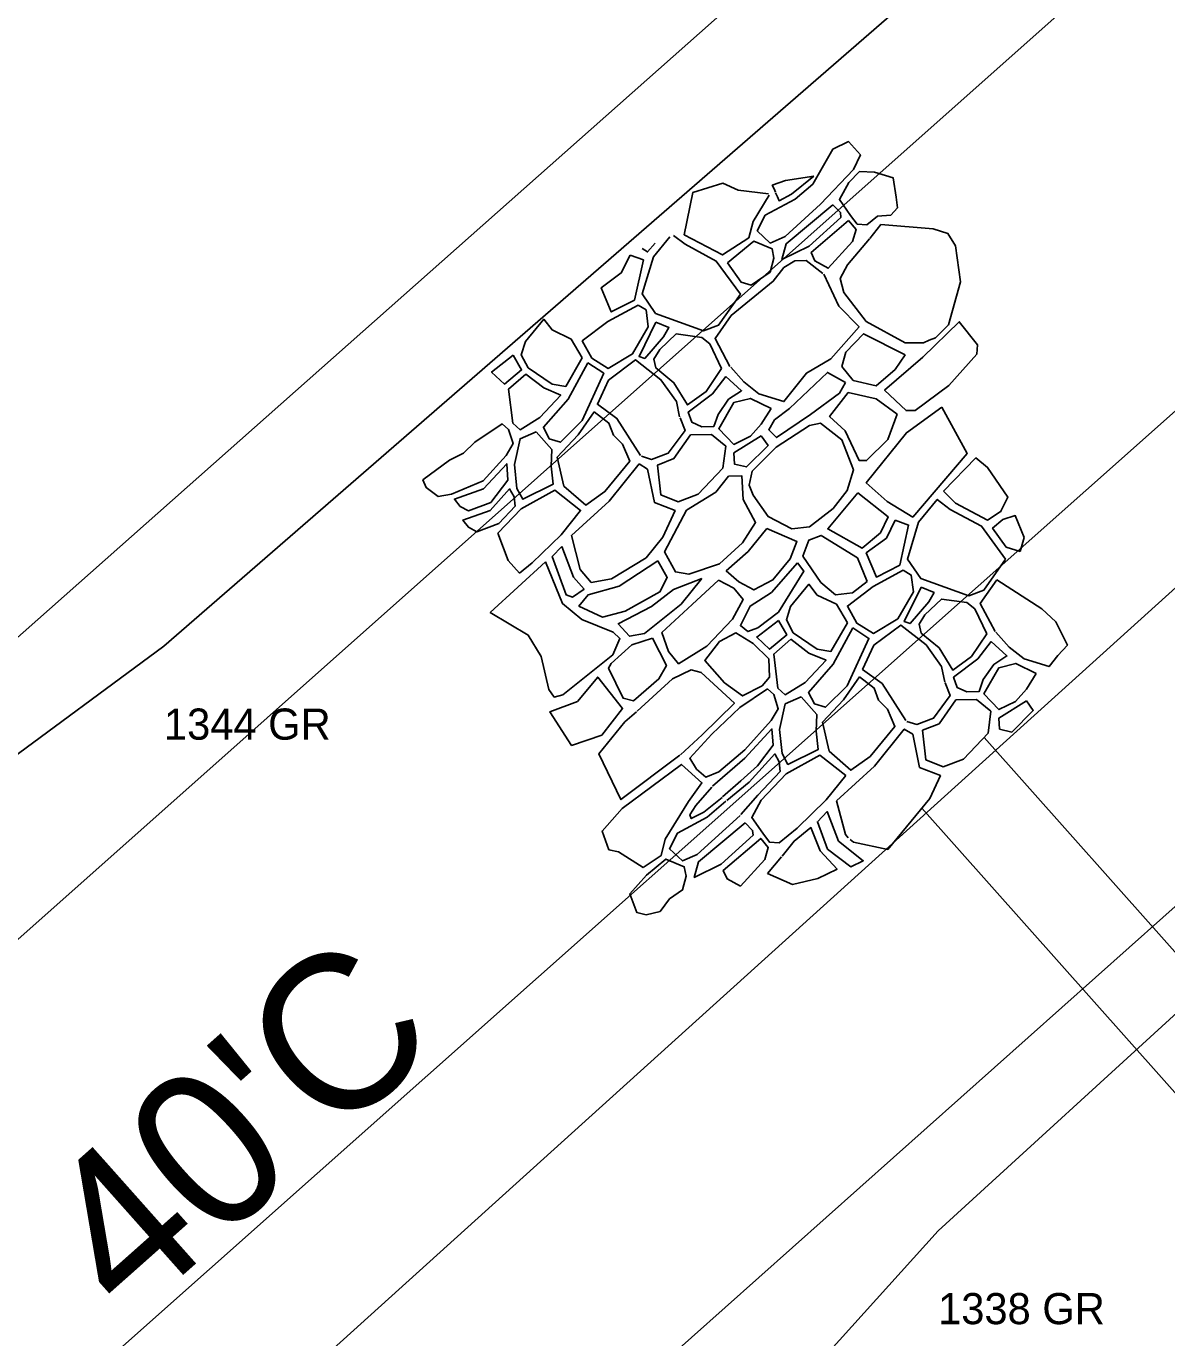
# Model space of a CAD drawing. Extents: x 50001 to 56005, y 49075 to 53926.
# Drawn here: x 53395.53 to 53432.14, y 51442.52 to 51484.63 of the extents above; entities that cross this region are included whole.
import ezdxf

# ---------------------------------------------------------------- set-up
doc = ezdxf.new("R2010")
doc.units = 0
for name, color, linetype in [('Level 1', 7, 'Continuous'), ('Level 11', 7, 'Continuous'), ('Level 16', 7, 'Continuous'), ('Level 18', 7, 'Continuous'), ('Level 3', 7, 'Continuous'), ('Level 57', 7, 'Continuous'), ('Level 7', 7, 'Continuous'), ('Level 8', 7, 'Continuous')]:
    doc.layers.add(name, color=color, linetype=linetype)

msp = doc.modelspace()

# ---------------------------------------------------------------- linework, layer by layer
at = {"layer": 'Level 1'}
msp.add_line((52544.807, 50683.302), (55534.583, 53340.862), dxfattribs=at)
at = {"layer": 'Level 11'}
msp.add_line((53157.705, 51254.454), (53424.495, 51490.929), dxfattribs=at)
at = {"layer": 'Level 16'}
for points in [[(53420.783, 51479.562), (53421.418, 51480.678), (53421.926, 51480.925), (53422.308, 51480.501), (53422.089, 51480.027), (53421.028, 51478.913)], [(53422.273, 51479.969), (53421.938, 51479.616), (53421.636, 51479.068), (53421.993, 51478.555), (53422.205, 51478.275), (53422.518, 51478.253), (53422.854, 51478.526)], [(53422.273, 51479.969), (53422.759, 51479.947), (53423.357, 51479.761), (53423.455, 51479.144), (53423.496, 51478.796), (53423.286, 51478.563), (53422.854, 51478.526)], [(53416.651, 51477.927), (53416.926, 51479.286), (53417.888, 51479.595), (53418.382, 51479.368), (53419.357, 51479.242)], [(53420.783, 51479.562), (53420.209, 51479.076), (53419.253, 51478.561), (53418.995, 51478.058), (53419.411, 51477.667), (53419.889, 51477.875), (53421.028, 51478.913)], [(53419.583, 51479.306), (53419.535, 51479.403), (53419.477, 51479.521), (53419.905, 51479.678), (53420.809, 51479.811)], [(53419.583, 51479.277), (53419.646, 51479.149), (53419.695, 51479.027), (53420.099, 51479.236), (53420.809, 51479.811)], [(53420.769, 51479.786), (53420.7, 51479.726)], [(53416.651, 51477.927), (53417.879, 51477.285), (53418.725, 51477.837), (53418.861, 51478.364), (53419.377, 51479.201)], [(53416.195, 51477.863), (53415.662, 51477.221), (53415.305, 51476.032), (53415.733, 51475.408), (53417.276, 51474.846), (53417.754, 51475.031), (53418.454, 51476.024), (53417.683, 51477.089), (53416.679, 51477.627), (53416.308, 51477.91)], [(53422.609, 51477.818), (53422.965, 51478.264)], [(53424.513, 51474.547), (53424.717, 51474.622), (53425.13, 51475.041), (53425.518, 51476.424), (53425.359, 51477.579), (53425.117, 51477.977), (53424.64, 51478.121), (53422.965, 51478.264)], [(53415.302, 51477.488), (53415.478, 51477.38), (53415.72, 51477.663)], [(53424.513, 51474.547), (53424.334, 51474.461), (53423.746, 51474.461), (53422.487, 51475.152), (53421.775, 51476.075), (53421.66, 51476.526), (53421.891, 51476.967), (53422.594, 51477.802)], [(53421.102, 51476.692), (53420.562, 51477.104), (53420.207, 51477.092), (53419.851, 51476.883), (53419.508, 51476.442), (53418.159, 51475.337), (53417.643, 51474.602), (53418.12, 51473.706)], [(53421.128, 51476.666), (53421.617, 51475.645), (53422.267, 51474.973), (53421.363, 51473.944), (53420.575, 51473.491), (53419.85, 51472.577), (53419.052, 51472.828), (53418.57, 51473.206), (53418.146, 51473.68)], [(53424.311, 51474.007), (53425.478, 51475.141), (53426.068, 51474.396), (53426.043, 51474.104), (53425.149, 51473.095)], [(53416.503, 51472.083), (53416.404, 51472.579), (53415.902, 51473.276), (53415.094, 51473.913), (53414.224, 51473.262), (53413.867, 51472.49), (53414.492, 51472.037), (53415.254, 51470.847)], [(53424.311, 51474.007), (53423.083, 51472.938), (53423.775, 51472.288), (53424.069, 51472.288), (53425.149, 51473.095)], [(53416.518, 51472.057), (53416.68, 51471.651), (53416.142, 51470.923), (53415.605, 51470.722), (53415.281, 51470.819)], [(53410.199, 51470.031), (53410.936, 51470.846), (53411.16, 51471.226), (53411.015, 51471.684), (53410.814, 51471.862), (53409.931, 51471.269), (53409.568, 51470.924)], [(53410.199, 51470.031), (53409.185, 51469.609), (53408.752, 51469.525), (53408.368, 51469.815), (53408.267, 51470.064), (53409.122, 51470.698), (53409.568, 51470.924)], [(53424.97, 51469.704), (53426.012, 51470.766), (53426.391, 51470.465), (53427.042, 51469.504), (53426.808, 51469.037)], [(53410.212, 51469.774), (53410.958, 51470.578), (53410.991, 51470.052), (53410.445, 51469.337)], [(53410.445, 51469.337), (53409.725, 51469.065), (53409.459, 51469.212), (53409.278, 51469.444), (53410.212, 51469.774)], [(53410.704, 51468.662), (53411.225, 51469.215), (53411.191, 51469.516), (53411.046, 51469.773), (53410.424, 51469.082)], [(53411.362, 51467.065), (53411.77, 51467.394), (53412.698, 51468.3), (53413.325, 51469.083), (53412.499, 51469.73), (53411.414, 51469.137), (53410.667, 51468.348)], [(53424.97, 51469.704), (53425.362, 51469.311), (53426.391, 51468.774), (53426.828, 51469.059)], [(53410.704, 51468.662), (53409.994, 51468.394), (53409.728, 51468.54), (53409.547, 51468.773), (53410.424, 51469.082)], [(53426.875, 51468.786), (53426.55, 51468.516), (53426.99, 51467.904), (53427.436, 51467.768)], [(53426.875, 51468.786), (53427.277, 51468.917), (53427.558, 51468.217), (53427.436, 51467.768)], [(53410.667, 51468.348), (53411.002, 51467.47), (53411.362, 51467.065)], [(53412.199, 51467.429), (53410.428, 51465.809), (53411.648, 51465.079), (53412.064, 51464.387), (53412.305, 51463.327), (53412.481, 51463.087), (53412.756, 51463.158)], [(53412.199, 51467.429), (53412.743, 51466.092), (53413.364, 51465.576), (53414.376, 51465.177), (53414.586, 51464.967), (53414.364, 51464.45), (53412.756, 51463.158)], [(53426.689, 51466.852), (53426.155, 51466.09), (53426.632, 51465.195)], [(53428.644, 51464.423), (53428.953, 51464.758), (53428.58, 51465.507), (53428.132, 51465.924), (53426.689, 51466.852)], [(53425.015, 51463.572), (53424.915, 51464.067), (53424.414, 51464.765), (53423.606, 51465.401), (53422.735, 51464.751), (53422.379, 51463.978), (53423.003, 51463.526), (53423.766, 51462.336)], [(53428.644, 51464.423), (53428.361, 51464.066), (53427.564, 51464.317), (53427.081, 51464.694), (53426.658, 51465.169)], [(53414.003, 51461.87), (53414.674, 51462.725), (53413.877, 51463.732), (53413.228, 51462.95)], [(53416.532, 51461.238), (53417.224, 51461.874), (53418.264, 51462.891), (53417.192, 51463.873), (53416.88, 51463.962), (53416.276, 51463.671), (53415.137, 51462.632)], [(53425.03, 51463.545), (53425.192, 51463.139), (53424.654, 51462.411), (53424.116, 51462.21), (53423.793, 51462.307)], [(53414.003, 51461.87), (53413.035, 51461.534), (53412.342, 51462.615), (53413.228, 51462.95)], [(53415.12, 51462.615), (53414.749, 51462.296), (53413.914, 51461.266), (53414.623, 51459.796), (53416.514, 51461.22)], [(53417.563, 51460.225), (53418.597, 51461.127), (53419.469, 51462.066), (53419.502, 51461.541), (53418.999, 51460.881), (53418.473, 51460.4), (53417.883, 51459.886)], [(53421.914, 51458.572), (53421.825, 51458.677), (53421.542, 51459.762), (53422.755, 51460.87), (53423.715, 51462.062), (53423.989, 51461.894), (53424.209, 51460.83), (53424.873, 51460.567), (53424.538, 51459.835)], [(53418.474, 51459.314), (53419.02, 51459.943), (53419.736, 51460.703), (53419.703, 51461.005), (53419.558, 51461.262), (53418.741, 51460.356), (53418.018, 51459.769)], [(53415.333, 51457.622), (53415.908, 51457.997), (53416.043, 51458.524), (53416.792, 51459.738), (53417.221, 51460.338), (53416.561, 51460.926), (53414.665, 51459.512)], [(53417.538, 51460.2), (53417.025, 51459.603), (53416.828, 51459.309), (53416.877, 51459.186), (53417.282, 51459.395), (53417.865, 51459.868)], [(53421.977, 51458.513), (53422.086, 51458.428), (53423.184, 51458.199), (53424.538, 51459.835)], [(53415.333, 51457.622), (53414.542, 51458.115), (53414.238, 51458.188), (53414.016, 51458.784), (53414.665, 51459.512)], [(53417.993, 51459.744), (53417.392, 51459.236), (53416.435, 51458.72), (53416.178, 51458.218), (53416.594, 51457.826), (53417.072, 51458.035), (53418.449, 51459.289)], [(53421.248, 51458.205), (53420.93, 51459.087), (53421.236, 51459.414), (53421.599, 51458.463)], [(53418.455, 51457.02), (53419.24, 51457.878), (53419.351, 51458.258), (53419.106, 51458.552), (53417.904, 51457.521), (53418.027, 51457.252), (53418.455, 51457.02)], [(53419.791, 51457.977), (53420.181, 51458.465), (53420.719, 51458.897), (53421.02, 51458.156)], [(53420.133, 51457.076), (53420.939, 51457.265), (53421.561, 51457.566), (53421.02, 51458.156)], [(53421.248, 51458.205), (53421.996, 51457.637), (53422.4, 51457.832), (53421.599, 51458.463)], [(53416.176, 51456.612), (53416.593, 51456.895), (53416.716, 51457.336), (53416.655, 51457.642), (53416.067, 51457.887), (53415.444, 51457.372)], [(53419.325, 51457.426), (53419.776, 51457.962)], [(53416.176, 51456.612), (53415.878, 51456.206), (53415.432, 51456.1), (53415.128, 51456.172), (53414.906, 51456.769), (53415.444, 51457.372)], [(53419.325, 51457.426), (53420.133, 51457.076)]]:
    msp.add_lwpolyline(points, dxfattribs=at)
for points in [[(53421.422, 51478.894), (53419.926, 51477.643), (53419.79, 51477.14), (53420.661, 51477.57), (53421.679, 51478.49), (53421.667, 51478.649)], [(53421.924, 51478.392), (53420.722, 51477.362), (53420.844, 51477.092), (53421.273, 51476.86), (53422.058, 51477.719), (53422.168, 51478.099)], [(53418.038, 51477.028), (53418.479, 51476.416), (53418.797, 51476.318), (53419.41, 51476.735), (53419.533, 51477.177), (53419.472, 51477.483), (53418.884, 51477.727)], [(53414.914, 51477.282), (53415.343, 51477.123), (53415.06, 51475.836), (53414.312, 51475.455), (53413.982, 51476.227), (53414.632, 51476.706)], [(53415.17, 51475.677), (53414.201, 51475.149), (53413.38, 51474.523), (53413.685, 51473.972), (53414.212, 51473.642), (53414.997, 51474.108), (53415.5, 51474.979), (53415.427, 51475.518)], [(53413.379, 51473.984), (53413.024, 51474.584), (53412.412, 51474.877), (53412.143, 51475.22), (53411.554, 51474.509), (53411.419, 51474.08), (53411.639, 51473.664), (53412.41, 51473.138), (53412.851, 51473.065)], [(53415.745, 51475.126), (53415.205, 51474.023), (53415.388, 51473.962), (53415.99, 51474.661), (53416.161, 51474.955)], [(53417.851, 51473.634), (53417.36, 51472.898), (53416.759, 51472.469), (53416.319, 51473.179), (53415.743, 51473.656), (53415.682, 51473.938), (53415.867, 51474.244), (53416.394, 51474.747), (53417.215, 51474.638), (53417.472, 51474.43)], [(53423.746, 51474.083), (53422.403, 51474.753), (53421.835, 51474.165), (53421.709, 51473.703), (53422.076, 51473.252), (53422.81, 51473.085), (53423.42, 51473.61)], [(53411.163, 51474.064), (53410.47, 51473.526), (53410.883, 51473.136), (53411.431, 51473.595)], [(53413.554, 51473.821), (53412.927, 51472.658), (53412.132, 51471.752), (53412.322, 51471.383), (53412.679, 51471.272), (53413.373, 51471.966), (53414.067, 51473.486)], [(53411.565, 51473.461), (53411.017, 51472.98), (53411.149, 51471.885), (53411.384, 51471.673), (53412.021, 51472.065), (53412.692, 51472.78), (53412.145, 51473.014)], [(53417.993, 51473.383), (53417.562, 51472.827), (53416.784, 51472.238), (53416.899, 51471.913), (53417.214, 51471.766), (53417.602, 51471.777), (53417.739, 51472.166), (53418.076, 51472.649), (53418.496, 51472.922)], [(53421.824, 51473.188), (53421.247, 51473.513), (53420.028, 51472.357), (53419.555, 51471.989), (53419.366, 51471.674), (53419.618, 51471.422), (53420.71, 51472.158), (53421.635, 51472.852)], [(53423.492, 51472.172), (53422.81, 51472.665), (53421.918, 51472.863), (53421.319, 51472.096), (53421.822, 51471.635), (53422.272, 51470.68), (53422.503, 51470.68), (53423.186, 51471.363)], [(53419.44, 51472.356), (53418.779, 51472.681), (53418.244, 51472.544), (53417.76, 51471.704), (53418.242, 51471.2), (53418.778, 51471.463), (53419.125, 51471.852)], [(53424.925, 51472.398), (53423.784, 51471.576), (53422.496, 51469.97), (53423.169, 51469.37), (53423.989, 51468.869), (53425.732, 51470.905)], [(53413.764, 51472.245), (53413.249, 51471.507), (53412.578, 51470.792), (53412.789, 51469.865), (53413.493, 51469.251), (53414.108, 51469.687), (53414.902, 51470.66), (53414.668, 51471.207), (53414.378, 51471.498), (53414.233, 51471.888)], [(53411.898, 51471.606), (53411.383, 51471.382), (53411.204, 51470.555), (53411.281, 51469.785), (53411.471, 51469.439), (53412.443, 51469.92), (53412.377, 51470.501), (53412.4, 51471.037)], [(53421.025, 51471.886), (53420.678, 51471.812), (53419.607, 51471.118), (53418.829, 51470.34), (53418.734, 51469.889), (53418.86, 51469.574), (53419.342, 51468.882), (53420.107, 51468.494), (53420.674, 51468.558), (53421.431, 51469.147), (53421.883, 51469.724), (53422.083, 51470.386), (53421.706, 51471.351)], [(53416.859, 51471.514), (53416.321, 51470.744), (53415.794, 51470.532), (53415.898, 51469.584), (53416.457, 51469.363), (53417.1, 51469.607), (53417.891, 51470.44), (53417.987, 51471.146), (53417.523, 51471.525)], [(53419.124, 51471.474), (53418.242, 51470.927), (53418.262, 51470.571), (53418.651, 51470.477), (53419.344, 51471.17)], [(53415.204, 51470.574), (53415.478, 51470.406), (53415.698, 51469.341), (53416.361, 51469.079), (53415.97, 51468.225), (53415.432, 51467.56), (53414.314, 51466.884), (53413.671, 51466.768), (53413.314, 51467.189), (53413.03, 51468.274), (53414.243, 51469.382)], [(53418.07, 51470.177), (53417.669, 51469.67), (53416.73, 51469.09), (53416.023, 51467.751), (53416.37, 51467.108), (53416.802, 51467.035), (53417.782, 51467.363), (53418.521, 51468.038), (53418.943, 51468.692), (53418.543, 51469.429), (53418.502, 51470.188)], [(53422.226, 51469.651), (53421.257, 51468.486), (53422.359, 51467.875), (53422.948, 51468.365), (53423.193, 51468.88)], [(53426.965, 51467.512), (53426.195, 51468.577), (53425.191, 51469.115), (53424.774, 51469.433), (53424.173, 51468.71), (53423.816, 51467.521), (53424.245, 51466.897), (53425.788, 51466.335), (53426.266, 51466.519)], [(53423.426, 51468.77), (53423.854, 51468.611), (53423.571, 51467.325), (53422.823, 51466.944), (53422.493, 51467.715), (53423.143, 51468.194)], [(53419.301, 51468.502), (53418.71, 51467.764), (53418.003, 51467.141), (53418.403, 51466.784), (53418.888, 51466.531), (53419.499, 51466.848), (53420.048, 51467.523), (53420.27, 51468.082)], [(53422.529, 51466.797), (53422.211, 51467.556), (53421.048, 51468.277), (53420.656, 51468.13), (53420.46, 51467.615), (53421.034, 51466.77), (53421.512, 51466.367), (53422.051, 51466.441)], [(53412.724, 51467.926), (53413.102, 51466.936), (53413.439, 51466.557), (53413.07, 51466.293), (53412.859, 51466.377), (53412.418, 51467.599)], [(53415.801, 51467.466), (53416.106, 51466.929), (53415.874, 51466.465), (53414.756, 51465.852), (53414.028, 51465.651), (53413.27, 51466.008), (53413.566, 51466.367), (53414.567, 51466.653)], [(53420.291, 51467.396), (53419.452, 51466.446), (53418.77, 51466.009), (53418.457, 51465.383), (53418.691, 51465.193), (53419.015, 51465.317), (53419.675, 51465.82), (53420.492, 51467.128)], [(53423.681, 51467.165), (53422.713, 51466.638), (53421.891, 51466.012), (53422.197, 51465.461), (53422.723, 51465.131), (53423.508, 51465.597), (53424.011, 51466.467), (53423.938, 51467.006)], [(53417.213, 51466.898), (53416.306, 51466.539), (53415.599, 51466.001), (53414.534, 51465.441), (53414.892, 51465.041), (53415.377, 51465.126), (53416.558, 51466.075)], [(53417.75, 51466.846), (53418.245, 51466.583), (53418.54, 51466.225), (53418.202, 51465.593), (53417.379, 51464.727), (53416.472, 51464.157), (53416.145, 51464.547), (53415.935, 51465.158), (53416.906, 51466.065)], [(53421.891, 51465.473), (53421.536, 51466.073), (53420.924, 51466.366), (53420.655, 51466.709), (53420.066, 51465.997), (53419.93, 51465.568), (53420.15, 51465.152), (53420.922, 51464.626), (53421.363, 51464.553)], [(53424.257, 51466.615), (53423.716, 51465.511), (53423.9, 51465.45), (53424.501, 51466.149), (53424.673, 51466.444)], [(53426.362, 51465.122), (53425.871, 51464.387), (53425.27, 51463.957), (53424.83, 51464.667), (53424.255, 51465.145), (53424.194, 51465.426), (53424.378, 51465.733), (53424.905, 51466.236), (53425.726, 51466.126), (53425.983, 51465.918)], [(53419.675, 51465.552), (53418.981, 51465.015), (53419.394, 51464.624), (53419.942, 51465.083)], [(53422.065, 51465.309), (53421.438, 51464.146), (53420.644, 51463.24), (53420.833, 51462.872), (53421.191, 51462.761), (53421.884, 51463.454), (53422.579, 51464.974)], [(53415.63, 51464.978), (53414.976, 51464.767), (53414.311, 51464.165), (53414.227, 51464.018), (53414.689, 51463.049), (53415.027, 51462.965), (53415.839, 51463.672), (53416.082, 51464.104)], [(53419.393, 51463.731), (53419.372, 51464.312), (53418.869, 51464.814), (53418.311, 51465.148), (53417.786, 51464.868), (53417.316, 51464.265), (53417.941, 51463.55), (53418.521, 51463.126), (53419.158, 51463.451)], [(53420.076, 51464.949), (53419.528, 51464.468), (53419.661, 51463.373), (53419.895, 51463.161), (53420.533, 51463.553), (53421.204, 51464.269), (53420.657, 51464.503)], [(53426.504, 51464.872), (53426.073, 51464.315), (53425.296, 51463.726), (53425.411, 51463.401), (53425.725, 51463.255), (53426.114, 51463.265), (53426.251, 51463.654), (53426.587, 51464.137), (53427.007, 51464.411)], [(53427.952, 51463.845), (53427.291, 51464.17), (53426.755, 51464.032), (53426.271, 51463.192), (53426.754, 51462.689), (53427.289, 51462.952), (53427.636, 51463.341)], [(53422.276, 51463.734), (53421.761, 51462.996), (53421.09, 51462.28), (53421.301, 51461.353), (53422.004, 51460.739), (53422.619, 51461.176), (53423.413, 51462.149), (53423.18, 51462.696), (53422.889, 51462.986), (53422.745, 51463.377)], [(53419.326, 51463.351), (53418.442, 51462.758), (53417.536, 51461.896), (53416.832, 51461.125), (53417.044, 51460.778), (53417.345, 51460.522), (53417.759, 51460.69), (53418.597, 51461.395), (53419.447, 51462.334), (53419.671, 51462.714), (53419.527, 51463.172)], [(53420.409, 51463.095), (53419.895, 51462.871), (53419.715, 51462.044), (53419.793, 51461.273), (53419.982, 51460.927), (53420.955, 51461.409), (53420.888, 51461.989), (53420.911, 51462.526)], [(53425.371, 51463.002), (53424.833, 51462.232), (53424.305, 51462.021), (53424.41, 51461.073), (53424.968, 51460.852), (53425.611, 51461.095), (53426.403, 51461.929), (53426.498, 51462.635), (53426.035, 51463.014)], [(53427.636, 51462.963), (53426.753, 51462.416), (53426.774, 51462.059), (53427.162, 51461.965), (53427.856, 51462.659)], [(53421.836, 51460.572), (53421.01, 51461.219), (53419.926, 51460.625), (53419.121, 51459.775), (53418.818, 51459.227), (53419.175, 51458.714), (53419.387, 51458.435), (53419.7, 51458.413), (53420.281, 51458.883), (53421.21, 51459.789)], [(53418.604, 51459.054), (53417.108, 51457.802), (53416.973, 51457.3), (53417.843, 51457.729), (53418.861, 51458.65), (53418.849, 51458.809)]]:
    msp.add_lwpolyline(points, close=True, dxfattribs=at)
at = {"layer": 'Level 18'}
msp.add_line((53402.158, 51439.255), (53439.259, 51472.776), dxfattribs=at)
at = {"layer": 'Level 3'}
for p, q in [((53162.497, 51248.316), (53434.092, 51489.844)), ((53179.352, 51230.724), (53449.718, 51471.806))]:
    msp.add_line(p, q, dxfattribs=at)
at = {"layer": 'Level 7'}
for p, q in [((53431.716, 51492.319), (53399.953, 51464.721)), ((53424.8, 51445.953), (53449.946, 51468.944)), ((53399.953, 51464.721), (53374.288, 51445.784)), ((53399.036, 51417.365), (53424.8, 51445.953))]:
    msp.add_line(p, q, dxfattribs=at)
at = {"layer": 'Level 8'}
for p, q in [((53439.059, 51447.413), (53426.275, 51461.794)), ((53436.816, 51445.42), (53424.28, 51459.523))]:
    msp.add_line(p, q, dxfattribs=at)

# ---------------------------------------------------------------- texts
at = {"layer": 'Level 18'}
msp.add_text("40'C", height=5, rotation=41.6334, dxfattribs=at).set_placement((53398.836, 51442.992))
at = {"layer": 'Level 57'}
for s, p in [('1344 GR', (53399.953, 51461.721)), ('1338 GR', (53424.8, 51442.953))]:
    msp.add_text(s, height=1, dxfattribs=at).set_placement(p)

doc.saveas('drawing.dxf')
